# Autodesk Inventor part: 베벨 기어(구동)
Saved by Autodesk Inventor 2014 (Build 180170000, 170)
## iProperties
Created: 2026-05
Part Number: 베벨 기어(구동)
Material: 강철, 합금
Document SubType Name: Modeling
Designer: dg
Density: 7.85 g/cm^3
Appearance: 반연마
Mass: 339.607 g
Surface Area: 144.418 cm^2
Volume: 43.262 cm^3
Author: jhkim
Creation Date: 2026-04-23
Sending System: Autodesk Inventor 2027
Preprocessor: ST-DEVELOPER v20.1
Author: dg
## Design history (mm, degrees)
node "베벨 기어(구동)1"
body "Solid1"
node "기준1"
